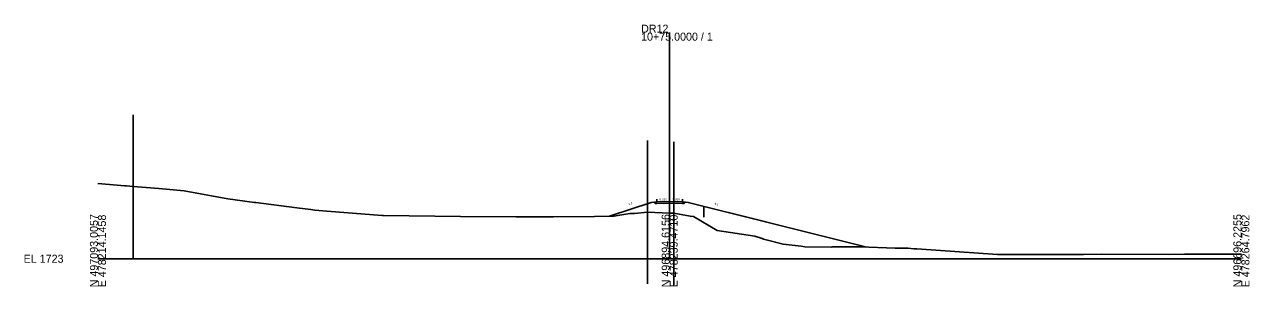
# Model space of a CAD drawing. Extents: x -26 to 403, y -10 to 3574.
# Drawn here: x -25.7 to 402.8, y 1490.3 to 1581.8 of the extents above; entities that cross this region are included whole.
import ezdxf

# ---------------------------------------------------------------- set-up
doc = ezdxf.new("R2010")
doc.units = 0
for name, color, linetype in [('Exist Cross Section Cell', 7, 'Continuous'), ('Exist XS Center Line Elevation Label', 7, 'Continuous'), ('Exist XS Ground Line', 7, 'Continuous'), ('Prop XS Earthwork Shape', 7, 'Continuous'), ('Prop XS EOT Tick Mark', 7, 'Continuous'), ('Prop XS Finish Grade', 7, 'Continuous'), ('Prop XS Finish Grade Earthwork', 7, 'Continuous'), ('Prop XS Finish Grade Pavement', 7, 'Continuous'), ('Prop XS Pvmt Edge Slope', 7, 'Continuous'), ('Prop XS SE Text', 7, 'Continuous'), ('Prop XS Shoulder Borrow Shape', 7, 'Continuous'), ('Prop XS Side Slope Text', 7, 'Continuous'), ('Prop XS Subgrade Earthwork', 7, 'Continuous'), ('Scratch_Level_0', 7, 'Continuous'), ('Scratch_Level_1', 7, 'Continuous'), ('Scratch_Level_4', 7, 'Continuous')]:
    doc.layers.add(name, color=color, linetype=linetype)

msp = doc.modelspace()

# ---------------------------------------------------------------- linework, layer by layer
at = {"layer": 'Exist Cross Section Cell'}
for p, q in [((200, 1500), (200, 1578.98)), ((0, 1500), (200, 1500)), ((200, 1500), (400, 1500))]:
    msp.add_line(p, q, dxfattribs=at)
at = {"layer": 'Exist XS Ground Line'}
msp.add_lwpolyline([(0, 1526.33), (9.45, 1525.48), (9.94, 1525.43), (12.3, 1525.29), (16.86, 1524.91), (21.34, 1524.48), (30.17, 1523.69), (45.45, 1520.88), (54.8, 1519.7), (55.24, 1519.65), (69.52, 1517.79), (74.43, 1517.14), (75.85, 1516.94), (80.02, 1516.65), (99.48, 1515.14), (99.84, 1515.13), (126.79, 1514.74), (146.15, 1514.62), (155.21, 1514.62), (156.57, 1514.6), (159.33, 1514.58), (173.76, 1514.71), (180.44, 1514.86), (186.07, 1515.76), (187.73, 1515.81), (192.22, 1516.28), (200, 1515.93), (201.5, 1515.87), (207.2, 1514.88), (208.33, 1514.71), (216.62, 1509.87), (229.78, 1507.86), (232.35, 1507.06), (232.86, 1506.89), (234.65, 1506.41), (239.67, 1505.05), (246.04, 1504.38), (247.23, 1504.18), (256.65, 1504.09), (256.97, 1504.11), (266.66, 1504.14), (278.83, 1503.72), (283.4, 1503.69), (285.36, 1503.51), (285.74, 1503.5), (286.47, 1503.46), (314.72, 1501.48), (321.89, 1501.53), (344.81, 1501.52), (350.97, 1501.55), (374.89, 1501.53), (380.12, 1501.56), (400, 1501.55)], dxfattribs=at)
at = {"layer": 'Prop XS Earthwork Shape'}
msp.add_lwpolyline([(178.91, 1514.83), (180.44, 1514.86), (186.07, 1515.76), (187.73, 1515.81), (192.22, 1516.28), (200, 1515.93), (201.5, 1515.87), (207.2, 1514.88), (208.33, 1514.71), (216.62, 1509.87), (229.78, 1507.86), (232.35, 1507.06), (232.86, 1506.89), (234.65, 1506.41), (239.67, 1505.05), (246.04, 1504.38), (247.23, 1504.18), (256.65, 1504.09), (256.97, 1504.11), (266.66, 1504.14), (269.01, 1504.06), (206.5, 1519.69), (205.52, 1519.77), (205.05, 1519.3), (204.5, 1519.31), (200, 1519.4), (195.5, 1519.31), (194.95, 1519.3), (194.48, 1519.77), (193.5, 1519.69)], close=True, dxfattribs=at)
at = {"layer": 'Prop XS EOT Tick Mark'}
for p, q in [((195.5, 1519.85), (195.5, 1520.85)), ((204.5, 1519.85), (204.5, 1520.85))]:
    msp.add_line(p, q, dxfattribs=at)
at = {"layer": 'Prop XS Finish Grade'}
for p, q in [((195.5, 1519.85), (194.48, 1519.77)), ((204.5, 1519.85), (205.52, 1519.77))]:
    msp.add_line(p, q, dxfattribs=at)
at = {"layer": 'Prop XS Finish Grade Earthwork'}
for p, q in [((193.5, 1519.69), (178.91, 1514.83)), ((194.48, 1519.77), (193.5, 1519.69)), ((205.52, 1519.77), (206.5, 1519.69)), ((206.5, 1519.69), (269.01, 1504.06))]:
    msp.add_line(p, q, dxfattribs=at)
at = {"layer": 'Prop XS Finish Grade Pavement'}
for p, q in [((195.5, 1519.85), (200, 1519.94)), ((200, 1519.94), (204.5, 1519.85))]:
    msp.add_line(p, q, dxfattribs=at)
at = {"layer": 'Prop XS Pvmt Edge Slope'}
for p, q in [((195.5, 1519.85), (194.95, 1519.3)), ((204.5, 1519.85), (205.05, 1519.3))]:
    msp.add_line(p, q, dxfattribs=at)
at = {"layer": 'Prop XS Shoulder Borrow Shape'}
for points in [[(195.5, 1519.85), (194.48, 1519.77), (194.95, 1519.3)], [(204.5, 1519.85), (205.52, 1519.77), (205.05, 1519.3)]]:
    msp.add_lwpolyline(points, close=True, dxfattribs=at)
at = {"layer": 'Prop XS Subgrade Earthwork'}
for p, q in [((194.95, 1519.3), (194.48, 1519.77)), ((195.5, 1519.31), (194.95, 1519.3)), ((200, 1519.4), (195.5, 1519.31)), ((200, 1519.4), (204.5, 1519.31)), ((204.5, 1519.31), (205.05, 1519.3)), ((205.05, 1519.3), (205.52, 1519.77))]:
    msp.add_line(p, q, dxfattribs=at)
at = {"layer": 'Scratch_Level_0'}
msp.add_line((212, 1518.31), (212, 1514.47), dxfattribs=at)
at = {"layer": 'Scratch_Level_1'}
for p, q in [((12.3, 1550.29), (12.3, 1500.29)), ((192.22, 1541.28), (192.22, 1491.28)), ((201.5, 1540.87), (201.5, 1490.87))]:
    msp.add_line(p, q, dxfattribs=at)
at = {"layer": 'Scratch_Level_4'}
for q in [(233.64, 1512.9), (269.01, 1504.06)]:
    msp.add_line((206.5, 1519.69), q, dxfattribs=at)

# ---------------------------------------------------------------- texts
at = {"layer": 'Exist Cross Section Cell'}
for s, p in [('DR12', (190, 1578.98)), ('10+75.0000 / 1', (190, 1576.18)), ('EL 1723', (-26, 1498.6))]:
    msp.add_text(s, height=2.8, dxfattribs=at).set_placement(p)
for s, p in [('N 497093.0057', (0, 1490)), ('E 478214.1458', (2.8, 1490)), ('N 496894.6156', (200, 1490)), ('E 478239.4710', (202.8, 1490)), ('N 496696.2255', (400, 1490)), ('E 478264.7962', (402.8, 1490))]:
    msp.add_text(s, height=2.8, rotation=90, dxfattribs=at).set_placement(p)
at = {"layer": 'Exist XS Center Line Elevation Label'}
msp.add_text('1738.93', height=0.75, dxfattribs=at).set_placement((198.22, 1513.18))
at = {"layer": 'Prop XS SE Text'}
for rotation, p in [(1.1458, (196.46, 1520.37)), (358.8542, (200.96, 1520.42))]:
    msp.add_text('0.020', height=0.75, rotation=rotation, dxfattribs=at).set_placement(p)
at = {"layer": 'Prop XS Side Slope Text'}
for s, rotation, p in [('3:1', 18.4349, (185.73, 1518.68)), ('4:1', 345.9638, (215.65, 1518.95))]:
    msp.add_text(s, height=0.75, rotation=rotation, dxfattribs=at).set_placement(p)

doc.saveas('drawing.dxf')
